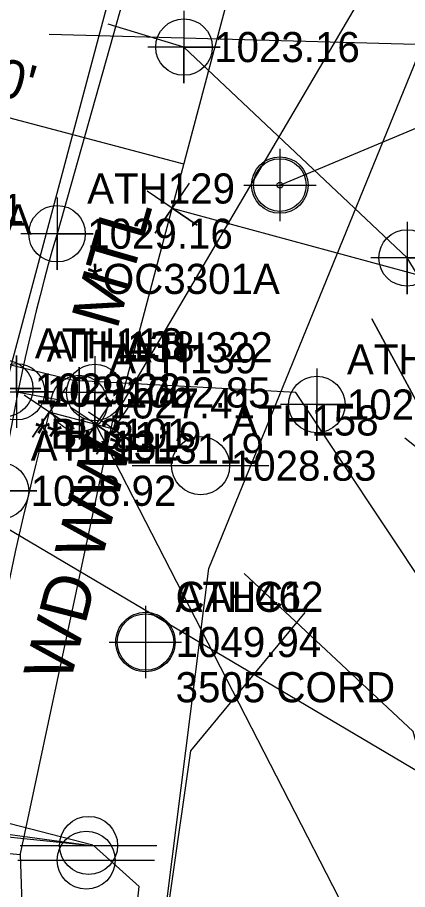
# Model space of a CAD drawing. Extents: x 1212084 to 1214478, y 765637 to 767408.
# Drawn here: x 1213335.7 to 1213368.1, y 766428.2 to 766500.6 of the extents above; entities that cross this region are included whole.
import ezdxf

# ---------------------------------------------------------------- set-up
doc = ezdxf.new("R2010")
doc.units = 0
for name, color, linetype in [('Cogo Default Point CELL', 7, 'Continuous'), ('COGO Default Point Elevation', 7, 'Continuous'), ('COGO Default Point Number', 7, 'Continuous'), ('Exist DTM Drainline Cogo Comment', 7, 'Continuous'), ('Exist DTM Drainline Cogo Elevation', 7, 'Continuous'), ('Exist DTM Drainline Cogo Number', 7, 'Continuous'), ('Exist DTM Drainline Cogo Point CELL', 7, 'Continuous'), ('Exist Guardrail', 7, 'Continuous'), ('Exist Guardrail Cogo Comment', 7, 'Continuous'), ('Exist Guardrail Cogo Elevation', 7, 'Continuous'), ('Exist Guardrail Cogo Number', 7, 'Continuous'), ('Exist Guardrail Cogo Point CELL', 7, 'Continuous'), ('Exist Guardrail Text', 7, 'Continuous'), ('Exist Hydro Jurisdictional Stream or Body of Water', 7, 'Continuous'), ('Exist Hydro River Flow Arrow CELL', 7, 'Continuous'), ('Exist Property Corner CELL', 7, 'Continuous'), ('Exist Property Line', 7, 'Continuous'), ('Exist Right of Way Line', 7, 'Continuous'), ('Exist Right of Way Width CELL', 7, 'Continuous'), ('Exist Roads EOP', 7, 'Continuous'), ('Exist Structure Major Bridge WW', 7, 'Continuous'), ('Exist Structure Major Bridge WW Cogo Comment', 7, 'Continuous'), ('Exist Structure Major Bridge WW Cogo Elevation', 7, 'Continuous'), ('Exist Structure Major Bridge WW Cogo Number', 7, 'Continuous'), ('Exist Structure Major Bridge WW Cogo Point CELL', 7, 'Continuous'), ('Exist Structure Major Bridge WW Text', 7, 'Continuous'), ('Exist Structure Major Deck Tunnel Box Culvert', 7, 'Continuous'), ('Exist Structure Major Deck Tunnel Box Culvert Cogo Comment', 7, 'Continuous'), ('Exist Structure Major Deck Tunnel Box Culvert Cogo Elevation', 7, 'Continuous'), ('Exist Structure Major Deck Tunnel Box Culvert Cogo Number', 7, 'Continuous'), ('Exist Structure Major Deck Tunnel Box Culvert Cogo Point CELL', 7, 'Continuous'), ('Exist Structure Major Deck Tunnel Box Culvert Leader', 7, 'Continuous'), ('Exist Utilities Other Located Object CELL', 7, 'Continuous'), ('Exist Utilities Other Located Object Text', 7, 'Continuous'), ('Exist Utilities Other Pole CELL', 7, 'Continuous'), ('Exist Utilities Other Pole Cogo Comment', 7, 'Continuous'), ('Exist Utilities Other Pole Cogo Elevation', 7, 'Continuous'), ('Exist Utilities Other Pole Cogo Number', 7, 'Continuous'), ('Exist Utilities Telephone Pole CELL', 7, 'Continuous'), ('Exist Utilities Telephone Pole Cogo Elevation', 7, 'Continuous'), ('Exist Utilities Telephone Pole Cogo Number', 7, 'Continuous'), ('Exist Utilities Telephone UG Cable SUE LOS C', 7, 'Continuous'), ('Exist Utilities Water UG Line SUE LOS B', 7, 'Continuous'), ('Exist Vegetation Woods Line', 7, 'Continuous')]:
    doc.layers.add(name, color=color, linetype=linetype)

msp = doc.modelspace()

# ---------------------------------------------------------------- linework, layer by layer
at = {"layer": 'Cogo Default Point CELL'}
for points in [[(1213357.472, 766489.673), (1213357.472, 766486.673)], [(1213354.472, 766486.673), (1213357.472, 766486.673)], [(1213357.472, 766486.673), (1213360.472, 766486.673)], [(1213357.472, 766486.673), (1213357.472, 766483.673)], [(1213346.321, 766451.757), (1213346.321, 766448.757)], [(1213343.321, 766448.757), (1213346.321, 766448.757)], [(1213346.321, 766448.757), (1213349.321, 766448.757)], [(1213346.321, 766448.757), (1213346.321, 766445.757)]]:
    msp.add_lwpolyline(points, dxfattribs=at)
for centre in [(1213357.472, 766486.673), (1213346.321, 766448.757)]:
    msp.add_circle(centre, 2.344, dxfattribs=at)
at = {"layer": 'Exist DTM Drainline Cogo Point CELL'}
for points in [[(1213349.519, 766501.124), (1213349.519, 766495.124), (1213349.519, 766498.124), (1213352.519, 766498.124), (1213346.519, 766498.124)], [(1213368.024, 766483.627), (1213368.024, 766477.627), (1213368.024, 766480.627), (1213371.024, 766480.627), (1213365.024, 766480.627)], [(1213342.113, 766472.463), (1213342.113, 766466.463), (1213342.113, 766469.463), (1213345.113, 766469.463), (1213339.113, 766469.463)], [(1213360.534, 766471.464), (1213360.534, 766465.464), (1213360.534, 766468.464), (1213363.534, 766468.464), (1213357.534, 766468.464)]]:
    msp.add_lwpolyline(points, dxfattribs=at)
for centre in [(1213349.519, 766498.124), (1213368.024, 766480.627), (1213342.113, 766469.463), (1213360.534, 766468.464)]:
    msp.add_circle(centre, 2.344, dxfattribs=at)
at = {"layer": 'Exist Guardrail'}
msp.add_lwpolyline([(1213362.87, 766562.366), (1213355.045, 766537.48), (1213346.209, 766508.26), (1213338.987, 766482.638)], dxfattribs=at)
msp.add_ellipse((1213477.634, 766441.504), major_axis=(-37.748, -146.236), ratio=0.957512, start_param=4.678118, end_param=4.958888, dxfattribs=at)
at = {"layer": 'Exist Guardrail Cogo Point CELL'}
for points in [[(1213338.987, 766485.638), (1213338.987, 766479.638), (1213338.987, 766482.638), (1213341.987, 766482.638), (1213335.987, 766482.638)], [(1213334.303, 766464.304), (1213334.303, 766458.304), (1213334.303, 766461.304), (1213337.303, 766461.304), (1213331.303, 766461.304)]]:
    msp.add_lwpolyline(points, dxfattribs=at)
for centre in [(1213338.987, 766482.638), (1213334.303, 766461.304)]:
    msp.add_circle(centre, 2.344, dxfattribs=at)
at = {"layer": 'Exist Hydro Jurisdictional Stream or Body of Water'}
for points in [[(1213458.541, 766244.269), (1213458.541, 766244.269), (1213446.982, 766261.332), (1213440.132, 766307.328), (1213429.645, 766367.831), (1213400.182, 766384.285), (1213389.875, 766405.51), (1213387.132, 766439.706), (1213382.822, 766456.43), (1213368.024, 766480.627), (1213349.519, 766498.124), (1213343.218, 766500.032)], [(1213526.436, 766209.954), (1213516.378, 766233.157), (1213480.9, 766229.639), (1213448.854, 766229.857), (1213432.873, 766257.536), (1213423.253, 766306.329), (1213418.782, 766357.325), (1213383.349, 766377.624), (1213374.57, 766398.221), (1213372.54, 766437.336), (1213369.822, 766452.855), (1213358.786, 766469.465), (1213340.365, 766470.464), (1213333.312, 766472.183)]]:
    msp.add_lwpolyline(points, dxfattribs=at)
at = {"layer": 'Exist Hydro River Flow Arrow CELL'}
msp.add_lwpolyline([(1213371.867, 766467.859), (1213372.073, 766465.824), (1213372.452, 766463.784), (1213373.004, 766461.766), (1213373.705, 766459.814), (1213374.615, 766457.976), (1213365.096, 766475.565), (1213374.615, 766457.976), (1213373.573, 766459.743), (1213372.323, 766461.397), (1213370.935, 766462.963), (1213369.434, 766464.397), (1213367.844, 766465.682)], dxfattribs=at)
at = {"layer": 'Exist Property Corner CELL'}
for p, q in [((1213348.537, 766484.754), (1213348.537, 766484.754)), ((1213338.344, 766467.838), (1213338.344, 766467.838)), ((1213338.344, 766467.838), (1213338.344, 766467.838)), ((1213342.206, 766466.81), (1213342.206, 766466.81)), ((1213343.659, 766466.424), (1213343.659, 766466.424)), ((1213343.659, 766466.424), (1213343.659, 766466.424))]:
    msp.add_line(p, q, dxfattribs=at)
for points in [[(1213349.937, 766486.825), (1213347.136, 766482.683), (1213348.537, 766484.754), (1213350.607, 766483.353), (1213346.466, 766486.155)], [(1213339.745, 766469.908), (1213336.944, 766465.767), (1213338.344, 766467.838), (1213340.415, 766466.437), (1213336.273, 766469.238)], [(1213339.745, 766469.908), (1213336.944, 766465.767), (1213338.344, 766467.838), (1213340.415, 766466.437), (1213336.273, 766469.238)], [(1213343.607, 766468.881), (1213340.806, 766464.739), (1213342.206, 766466.81), (1213344.277, 766465.409), (1213340.136, 766468.211)], [(1213345.06, 766468.494), (1213342.259, 766464.353), (1213343.659, 766466.424), (1213345.73, 766465.023), (1213341.589, 766467.824)], [(1213345.06, 766468.494), (1213342.259, 766464.353), (1213343.659, 766466.424), (1213345.73, 766465.023), (1213341.589, 766467.824)]]:
    msp.add_lwpolyline(points, dxfattribs=at)
at = {"layer": 'Exist Property Line'}
for p, q in [((1213348.537, 766484.754), (1213513.863, 766439.963)), ((1213458.487, 766240.467), (1213342.206, 766466.81))]:
    msp.add_line(p, q, dxfattribs=at)
at = {"layer": 'Exist Right of Way Line'}
for q in [(1213354.521, 766507.246), (1213338.344, 766467.838)]:
    msp.add_line((1213343.659, 766466.424), q, dxfattribs=at)
msp.add_arc((1213602.628, 766397.517), 273.479, 165.1, 175.1, dxfattribs=at)
at = {"layer": 'Exist Right of Way Width CELL'}
msp.add_line((1213349.506, 766488.397), (1213331.953, 766493.067), dxfattribs=at)
at = {"layer": 'Exist Roads EOP'}
msp.add_spline([(1213331.542, 766460.381), (1213328.202, 766439.131), (1213326.882, 766418.055), (1213328.894, 766392.003), (1213339.56, 766359.268), (1213347.201, 766343.262), (1213357.639, 766324.019), (1213372.578, 766298.933)], degree=3, dxfattribs=at)
at = {"layer": 'Exist Structure Major Bridge WW'}
msp.add_line((1213335.628, 766469.524), (1213340.825, 766468.554), dxfattribs=at)
at = {"layer": 'Exist Structure Major Bridge WW Cogo Point CELL'}
for points in [[(1213332.628, 766469.524), (1213338.628, 766469.524), (1213335.628, 766469.524), (1213335.628, 766472.524), (1213335.628, 766466.524)], [(1213337.825, 766468.554), (1213343.825, 766468.554), (1213340.825, 766468.554), (1213340.825, 766471.554), (1213340.825, 766465.554)]]:
    msp.add_lwpolyline(points, dxfattribs=at)
for centre in [(1213335.628, 766469.524), (1213340.825, 766468.554)]:
    msp.add_circle(centre, 2.344, dxfattribs=at)
at = {"layer": 'Exist Structure Major Deck Tunnel Box Culvert'}
msp.add_lwpolyline([(1213334.645, 766469.793), (1213316.583, 766474.725), (1213327.014, 766513.184), (1213344.974, 766508.526), (1213334.645, 766469.793)], dxfattribs=at)
at = {"layer": 'Exist Structure Major Deck Tunnel Box Culvert Cogo Point CELL'}
msp.add_lwpolyline([(1213331.645, 766469.793), (1213337.645, 766469.793), (1213334.645, 766469.793), (1213334.645, 766472.793), (1213334.645, 766466.793)], dxfattribs=at)
msp.add_circle((1213334.645, 766469.793), 2.344, dxfattribs=at)
at = {"layer": 'Exist Structure Major Deck Tunnel Box Culvert Leader'}
msp.add_line((1213338.336, 766499.181), (1213371.06, 766498.304), dxfattribs=at)
at = {"layer": 'Exist Utilities Other Located Object CELL'}
for radius in [2.18, 0.24]:
    msp.add_circle((1213357.472, 766486.673), radius, dxfattribs=at)
at = {"layer": 'Exist Utilities Other Located Object Text'}
for p, q in [((1213357.472, 766486.673), (1213475.622, 766536.167)), ((1213325.77, 766463.572), (1213448.139, 766391.086))]:
    msp.add_line(p, q, dxfattribs=at)
at = {"layer": 'Exist Utilities Other Pole CELL'}
msp.add_circle((1213346.321, 766448.757), 2.463, dxfattribs=at)
at = {"layer": 'Exist Utilities Telephone Pole CELL'}
for p, q in [((1213345.225, 766463.39), (1213356.562, 766463.39)), ((1213350.9, 766463.39), (1213350.9, 766463.39)), ((1213335.93, 766431.882), (1213347.268, 766431.882)), ((1213335.93, 766431.882), (1213347.268, 766431.882)), ((1213341.605, 766431.882), (1213341.605, 766431.882)), ((1213341.605, 766431.882), (1213341.605, 766431.882)), ((1213335.734, 766430.656), (1213347.072, 766430.656)), ((1213341.409, 766430.656), (1213341.409, 766430.656))]:
    msp.add_line(p, q, dxfattribs=at)
for centre in [(1213350.9, 766463.39), (1213341.605, 766431.882), (1213341.605, 766431.882), (1213341.409, 766430.656)]:
    msp.add_circle(centre, 2.407, dxfattribs=at)
at = {"layer": 'Exist Utilities Telephone UG Cable SUE LOS C'}
for points in [[(1213341.961, 766431.913), (1213328.103, 766435.473), (1213295.641, 766441.691), (1213265.182, 766443.402), (1213217.574, 766449.967), (1213193.007, 766453.229)], [(1213341.605, 766431.882), (1213320.666, 766434.715), (1213279.606, 766440.281), (1213251.305, 766443.555), (1213191.433, 766451.085)], [(1213341.605, 766431.882), (1213281.191, 766438.132), (1213247.983, 766441.734), (1213189.142, 766449.12)], [(1213446.992, 766189.676), (1213435.308, 766208.382), (1213408.347, 766256.096), (1213366.855, 766324.687), (1213348.111, 766370.479), (1213343.437, 766406.102), (1213345.806, 766428.476), (1213342.023, 766431.866)]]:
    msp.add_lwpolyline(points, dxfattribs=at)
at = {"layer": 'Exist Utilities Water UG Line SUE LOS B'}
for points in [[(1213442.485, 766187.899), (1213413.61, 766239.451), (1213383.654, 766291.968), (1213352.36, 766345.759), (1213337.483, 766385.325), (1213335.947, 766431.182), (1213343.643, 766467.236), (1213372.392, 766516.172), (1213376.297, 766543.269), (1213379.468, 766574.764), (1213363.657, 766578.488), (1213343.259, 766583.25), (1213356.595, 766631.997), (1213369.551, 766678.004), (1213389.41, 766743.157), (1213404.898, 766797.922), (1213408.97, 766818.968)], [(1213312.252, 766356.682), (1213342.315, 766369.143), (1213353.998, 766372.079), (1213350.927, 766383.418), (1213347.777, 766424.606), (1213351.576, 766454.854), (1213376.387, 766515.679), (1213382.751, 766545.226), (1213385.129, 766575.512), (1213387.127, 766612.966), (1213395.365, 766676.737), (1213413.112, 766741.363), (1213427.394, 766793.323), (1213430.959, 766811.701)], [(1213184.529, 766444.324), (1213200.218, 766443.309), (1213252.28, 766436.153), (1213295.464, 766435.489), (1213327.862, 766431.837), (1213335.949, 766431.121)]]:
    msp.add_lwpolyline(points, dxfattribs=at)
at = {"layer": 'Exist Vegetation Woods Line'}
for points in [[(1213432.962, 766248.974), (1213420.975, 766328.415), (1213414.483, 766355.395), (1213390.011, 766371.384), (1213377.026, 766386.872), (1213377.026, 766410.854), (1213368.536, 766441.332), (1213354.521, 766454.447)], [(1213396.358, 766281.528), (1213364.557, 766330.818), (1213349.574, 766361.795), (1213345.079, 766404.764), (1213350.073, 766439.738), (1213359.58, 766451.212)]]:
    msp.add_lwpolyline(points, dxfattribs=at)

# ---------------------------------------------------------------- texts
at = {"layer": 'COGO Default Point Elevation'}
msp.add_text('1049.94', height=2.5, dxfattribs=at).set_placement((1213348.821, 766447.507))
at = {"layer": 'COGO Default Point Number'}
msp.add_text('CALC1', height=2.5, dxfattribs=at).set_placement((1213348.821, 766451.257))
at = {"layer": 'Exist DTM Drainline Cogo Comment'}
msp.add_text('*BL4003A', height=2.5, dxfattribs=at).set_placement((1213321.829, 766482.569))
at = {"layer": 'Exist DTM Drainline Cogo Elevation'}
for s, p in [('1023.16', (1213352.019, 766496.874)), ('1022.85', (1213344.613, 766468.213)), ('1023.00', (1213363.034, 766467.214))]:
    msp.add_text(s, height=2.5, dxfattribs=at).set_placement(p)
at = {"layer": 'Exist DTM Drainline Cogo Number'}
for s, p in [('ATH322', (1213344.613, 766471.963)), ('ATH317', (1213363.034, 766470.964))]:
    msp.add_text(s, height=2.5, dxfattribs=at).set_placement(p)
at = {"layer": 'Exist Guardrail Cogo Comment'}
for s, p in [('*OC3301', (1213322.509, 766483.433)), ('*OC3301A', (1213341.487, 766477.638))]:
    msp.add_text(s, height=2.5, dxfattribs=at).set_placement(p)
at = {"layer": 'Exist Guardrail Cogo Elevation'}
for s, p in [('1029.16', (1213341.487, 766481.388)), ('1028.92', (1213336.803, 766460.054))]:
    msp.add_text(s, height=2.5, dxfattribs=at).set_placement(p)
at = {"layer": 'Exist Guardrail Cogo Number'}
for s, p in [('ATH129', (1213341.487, 766485.138)), ('ATH131', (1213336.803, 766463.804))]:
    msp.add_text(s, height=2.5, dxfattribs=at).set_placement(p)
at = {"layer": 'Exist Guardrail Text'}
msp.add_text('MTL', height=4, rotation=73.93732, dxfattribs=at).set_placement((1213343.958, 766474.581))
at = {"layer": 'Exist Right of Way Width CELL'}
msp.add_text("37.00'", height=3.2, rotation=345.1, dxfattribs=at).set_placement((1213325.551, 766496.349))
at = {"layer": 'Exist Structure Major Bridge WW Cogo Comment'}
for s, p in [('*BL3119', (1213338.128, 766464.524)), ('*EL3119', (1213343.325, 766463.554))]:
    msp.add_text(s, height=2.5, dxfattribs=at).set_placement(p)
at = {"layer": 'Exist Structure Major Bridge WW Cogo Elevation'}
for s, p in [('1028.76', (1213338.128, 766468.274)), ('1027.41', (1213343.325, 766467.304))]:
    msp.add_text(s, height=2.5, dxfattribs=at).set_placement(p)
at = {"layer": 'Exist Structure Major Bridge WW Cogo Number'}
for s, p in [('ATH138', (1213338.128, 766472.024)), ('ATH139', (1213343.325, 766471.054))]:
    msp.add_text(s, height=2.5, dxfattribs=at).set_placement(p)
at = {"layer": 'Exist Structure Major Bridge WW Text'}
msp.add_text('WD WW', height=4, rotation=75.52752, dxfattribs=at).set_placement((1213340.051, 766445.226))
at = {"layer": 'Exist Structure Major Deck Tunnel Box Culvert Cogo Comment'}
msp.add_text('*BL3101', height=2.5, dxfattribs=at).set_placement((1213337.145, 766464.793))
at = {"layer": 'Exist Structure Major Deck Tunnel Box Culvert Cogo Elevation'}
msp.add_text('1029.22', height=2.5, dxfattribs=at).set_placement((1213337.145, 766468.543))
at = {"layer": 'Exist Structure Major Deck Tunnel Box Culvert Cogo Number'}
msp.add_text('ATH118', height=2.5, dxfattribs=at).set_placement((1213337.145, 766472.293))
at = {"layer": 'Exist Utilities Other Pole Cogo Comment'}
msp.add_text('3505 CORD', height=2.5, dxfattribs=at).set_placement((1213348.821, 766443.757))
at = {"layer": 'Exist Utilities Other Pole Cogo Elevation'}
msp.add_text('1049.94', height=2.5, dxfattribs=at).set_placement((1213348.821, 766447.507))
at = {"layer": 'Exist Utilities Other Pole Cogo Number'}
msp.add_text('ATH462', height=2.5, dxfattribs=at).set_placement((1213348.821, 766451.257))
at = {"layer": 'Exist Utilities Telephone Pole Cogo Elevation'}
msp.add_text('1028.83', height=2.5, dxfattribs=at).set_placement((1213353.4, 766462.14))
at = {"layer": 'Exist Utilities Telephone Pole Cogo Number'}
msp.add_text('ATH158', height=2.5, dxfattribs=at).set_placement((1213353.4, 766465.89))

doc.saveas('drawing.dxf')
